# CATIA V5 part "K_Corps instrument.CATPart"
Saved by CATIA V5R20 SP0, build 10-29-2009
Part number: Corps instrument
Material "Noyer": density 609 kg/m3, Young's modulus 1.16e+10 Pa
Material "Noyer": density 609 kg/m3, Young's modulus 1.16e+10 Pa
Material "Sapin": density 500 kg/m3, Young's modulus 1.7e+10 Pa, Poisson ratio 0.45, thermal expansion 3.75e-06 1/K
Bounding box of the stored display mesh (mm): x -70 to 114.339, y -224.999 to 224.999, z -164 to 1030.632
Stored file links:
  G:\Khaled_CFAO_2011\ST2M\ST2M_GR2\amorin\Khaled\CAD_Modification\K_Corps instrument.CATPart
  C:\Program Files\Dassault Systemes\B20\win_b64\startup\materials\French\Catalog.CATMaterial
  C:\Program Files\Dassault Systemes\B20\win_b64\startup\materials\beech.jpg
  C:\Program Files\Dassault Systemes\B20\win_b64\startup\materials\wild_walnut.jpg
  C:\Program Files\Dassault Systemes\B20\win_b64\startup\materials\red_wood.jpg
  C:\Program Files\Dassault Systemes\B20\win_b64\startup\materials\mahogany.jpg
  C:\Program Files\Dassault Systemes\B20\win_b64\startup\materials\bright_oak.jpg
  C:\Program Files\Dassault Systemes\B20\win_b64\startup\materials\wild_cherry.jpg
  C:\Program Files\Dassault Systemes\B20\win_b64\startup\materials\pinetree.jpg
  C:\Program Files\Dassault Systemes\B20\win_b64\startup\materials\rosewood.jpg
  C:\Program Files\Dassault Systemes\B20\win_b64\startup\materials\walnut.jpg
  C:\Program Files\Dassault Systemes\B20\win_b64\startup\materials\alpin_fir.jpg
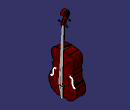
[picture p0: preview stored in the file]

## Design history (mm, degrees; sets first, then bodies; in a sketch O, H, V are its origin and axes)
Set1
  Plane1: type Angle, RefPlane yz-plane, Direction edge [face of Pad1 from Sketch1.L3 | end face of Pad1], Angle 5
Body1 (main body)
  Sketch1 on yz-plane, origin (0, 0, 0), H (0, 1, 0), V (0, 0, 1)
    arc A1 centre (-61, 0) radius 164 from (-217.1922, 50) to (-61, -164) ccw
    point P2 (-217.1922, 50)
    point P3 (-61, -164)
    line L1 (-61, -164) -> (-61, -154)
    point P4 (-61, -154)
    point P5 (0, 50)
    point P6 (61, -154)
    point P7 (61, -164)
    point P8 (217.1922, 50)
    point P9 (61, 0)
    arc A2 centre (61, 0) radius 164 from (217.1922, 50) to (61, -164) cw
    line L2 (61, -164) -> (61, -154)
    point P10 (0, 50)
    line L3 (-61, -154) -> (61, -154)
    arc A3 centre (-61, 0) radius 164 from (-217.1922, 50) to (-199.9767, 87.0717) cw
    point P12 (-204.3922, 79.5907)
    point P13 (-197.6963, 90.6097)
    line L4 (-200.0931, 94.1702) -> (-204.012, 99.9916)
    point P14 (-204.012, 99.9916)
    line L5 (-204.012, 99.9916) -> (-202.1596, 101.2916)
    point P15 (-202.1596, 101.2916)
    line L6 (-202.1596, 101.2916) -> (-196.9559, 99.2887)
    point P16 (-192.7457, 97.6682)
    arc A4 centre (-321.9325, 193.4393) radius 160.8146 from (-190.0619, 101.3986) to (-164.0477, 223.9964) ccw
    point P17 (-321.9325, 193.4393)
    arc A5 centre (-194.8558, 104.7446) radius 5.8462 from (-190.0619, 101.3986) to (-196.9559, 99.2887) cw
    point P18 (-190.0619, 101.3986)
    point P19 (-196.9559, 99.2887)
    arc A6 centre (-205.4985, 90.5313) radius 6.5161 from (-199.9767, 87.0717) to (-200.0931, 94.1702) ccw
    point P21 (-199.9767, 87.0717)
    point P22 (-200.0931, 94.1702)
    point P24 (-165.5658, 231)
    line L7 (-172.3837, 229.3623) -> (-176, 228.4936)
    point P25 (-176, 228.4936)
    line L8 (-176, 228.4936) -> (-177.6873, 231)
    point P26 (-177.6873, 231)
    line L9 (-177.6873, 231) -> (-171.3021, 235.481)
    point P27 (-167.4652, 238.1738)
    arc A7 centre (-170.7817, 222.6931) radius 6.8589 from (-164.0477, 223.9964) to (-172.3837, 229.3623) ccw
    point P28 (-164.0477, 223.9964)
    point P29 (-172.3837, 229.3623)
    axis line L10 (0, -177) -> (0, 597)
    point P31 (0, -177)
    point P33 (0, 489)
    arc A8 centre (-5.9488, -152.8379) radius 641.8655 from (0, 489) to (-108.317, 480.8119) ccw
    arc A9 centre (-94.4955, 395.258) radius 86.6631 from (-108.317, 480.8119) to (-181.1554, 396) ccw
    point P36 (-181.1554, 396)
    arc A10 centre (82.1641, 393.7455) radius 263.3292 from (-181.1554, 396) to (-157.7256, 285.14) ccw
    point P38 (-142.2045, 255.9015)
    point P39 (0, 489)
    point P40 (-108.317, 480.8119)
    arc A11 centre (-194.476, 268.502) radius 40.3412 from (-157.7256, 285.14) to (-171.3021, 235.481) cw
    point P41 (-157.7256, 285.14)
    point P42 (-171.3021, 235.481)
    point P44 (204.3922, 79.5907)
    point P45 (197.6963, 90.6097)
    point P46 (204.012, 99.9916)
    point P47 (202.1596, 101.2916)
    point P48 (192.7457, 97.6682)
    point P49 (190.0619, 101.3986)
    point P50 (196.9559, 99.2887)
    point P52 (199.9767, 87.0717)
    point P53 (200.0931, 94.1702)
    point P55 (165.5658, 231)
    point P56 (176, 228.4936)
    point P57 (177.6873, 231)
    point P58 (167.4652, 238.1738)
    point P59 (164.0477, 223.9964)
    point P60 (172.3837, 229.3623)
    point P62 (0, 489)
    point P64 (181.1554, 396)
    point P66 (142.2045, 255.9015)
    point P67 (0, 489)
    point P68 (108.317, 480.8119)
    point P69 (157.7256, 285.14)
    point P70 (171.3021, 235.481)
    line L11 (200.0931, 94.1702) -> (204.012, 99.9916)
    line L12 (204.012, 99.9916) -> (202.1596, 101.2916)
    line L13 (202.1596, 101.2916) -> (196.9559, 99.2887)
    arc A12 centre (321.9325, 193.4393) radius 160.8146 from (190.0619, 101.3986) to (164.0477, 223.9964) cw
    arc A13 centre (194.8558, 104.7446) radius 5.8462 from (190.0619, 101.3986) to (196.9559, 99.2887) ccw
    arc A14 centre (205.4985, 90.5313) radius 6.5161 from (199.9767, 87.0717) to (200.0931, 94.1702) cw
    line L14 (172.3837, 229.3623) -> (176, 228.4936)
    line L15 (176, 228.4936) -> (177.6873, 231)
    line L16 (177.6873, 231) -> (171.3021, 235.481)
    arc A15 centre (170.7817, 222.6931) radius 6.8589 from (164.0477, 223.9964) to (172.3837, 229.3623) cw
    arc A16 centre (5.9488, -152.8379) radius 641.8655 from (0, 489) to (108.317, 480.8119) cw
    arc A17 centre (94.4955, 395.258) radius 86.6631 from (108.317, 480.8119) to (181.1554, 396) cw
    arc A18 centre (-82.1641, 393.7455) radius 263.3292 from (181.1554, 396) to (157.7256, 285.14) cw
    arc A19 centre (194.476, 268.502) radius 40.3412 from (157.7256, 285.14) to (171.3021, 235.481) ccw
    point P74 (217.1922, 50)
    point P75 (204.3922, 79.5907)
    point P76 (199.9767, 87.0717)
    arc A20 centre (61, 0) radius 164 from (217.1922, 50) to (199.9767, 87.0717) ccw
    angle L4 L5 = 91.1128
    angle L6 L5 = 123.8872
    radius A5 = 5.8462
    radius A6 = 6.5161
    radius A7 = 6.8589
    radius A11 = 40.3412
    vertical: L1 V, L10 V
    coincidence: P5 V, P5 P10, A3 P12, P12 A1, P13 A1, P16 A3, L6 P9, A4 P16, L6 P16, A3 P13, L4 P13, P24 A4, L7 P17, P27 A4, L7 P24, P31 V, P33 L10, P38 L9, A10 P38, L9 P27
    symmetry: P4 P6 V, P3 P7 V, P2 P8 V, A1 A2 V, L1 L2 V, P5 P10 V, P12 P44 L10, P13 P45 L10, P14 P46 L10, P15 P47 L10, P16 P48 L10, P18 P49 L10, P19 P50 L10, P21 P52 L10, P22 P53 L10, P24 P55 L10, P25 P56 L10, P26 P57 L10, P27 P58 L10, P28 P59 L10, P29 P60 L10, P33 P62 L10, P36 P64 L10, P38 P66 L10, P39 P67 L10, P40 P68 L10, P41 P69 L10, P42 P70 L10, L4 L11 L10, L5 L12 L10, L6 L13 L10, A4 A12 L10, A5 A13 L10, A6 A14 L10, L7 L14 L10, L8 L15 L10, L9 L16 L10, A7 A15 L10, A8 A16 L10, A9 A17 L10, A10 A18 L10, A11 A19 L10, P2 P74 L10, P12 P75 L10, P21 P76 L10, A3 A20 L10
    horizontal: L3 H
    tangency: L4 A2, L5 A3, A4 A1, A5 L6, A5 A4, A6 A3, A6 L4, A7 L7, A7 A4, A9 L9, A10 A9, A9 A8, A11 A10, A11 L9
    parallelism: L8 L4, L9 L5
  Pad1: profile Sketch1, direction (1, 0, 0), length 70, mirrored extent
  Sketch2 on face of Pad1 from Sketch1.L3, origin (-8.5202, -2.8573, -154), H (1, 0, 0), V (0, -1, 0)
    point P1 (0, 0)
  Hole1: placed by Sketch2, at (-8.5202, -2.8573, -154) direction (0, 0, 1), diameter 34, depth 70, type TaperedType, Diameter 34, Sketch Sketch2, Profile a sketch, ThreadDepth 10, DiameterThread 37.4, Pas 1, Angle 5
  Fillet1: radius 3, on edge [start face of Pad1 | face of Pad1 from Sketch1.A1]; edge [start face of Pad1 | face of Pad1 from Sketch1.L3]; edge [start face of Pad1 | face of Pad1 from Sketch1.L2]; edge [start face of Pad1 | face of Pad1 from Sketch1.A2]
  Sketch3 on end face of Pad1, origin (70, 0, 0), H (0, 1, 0), V (0, 0, 1)
    spline S1 through (117.3427, 183.1693) (128, 185) (144, 173) (154.3427, 148.1693) (170.8675, 66.9958) (181, 61)
    spline S2 through (179, 51) (163, 62) (152, 91) (150, 113) (150, 137) (137.8996, 169.4934) (130.8996, 176.4934)
    arc A1 centre (122.784, 177.1161) radius 8.1394 from (117.3427, 183.1693) to (130.8996, 176.4934) ccw
    point P1 (130.8996, 176.4934)
    point P3 (117.3427, 183.1693)
    arc A2 centre (185.6857, 54.8629) radius 7.7214 from (179, 51) to (181, 61) ccw
    point P4 (181, 61)
    point P6 (179, 51)
    point P7 (-130.8996, 176.4934)
    point P9 (-117.3427, 183.1693)
    point P10 (-181, 61)
    point P12 (-179, 51)
    spline S3 through (-117.3427, 183.1693) (-128, 185) (-144, 173) (-154.3427, 148.1693) (-170.8675, 66.9958) (-181, 61)
    spline S4 through (-179, 51) (-163, 62) (-152, 91) (-150, 113) (-150, 137) (-137.8996, 169.4934) (-130.8996, 176.4934)
    arc A3 centre (-122.784, 177.1161) radius 8.1394 from (-117.3427, 183.1693) to (-130.8996, 176.4934) cw
    arc A4 centre (-185.6857, 54.8629) radius 7.7214 from (-179, 51) to (-181, 61) cw
    point P13 (130.8996, 176.4934)
    point P14 (117.3427, 183.1693)
    point P15 (181, 61)
    point P16 (179, 51)
    point P17 (-181, 61)
    point P18 (-117.3427, 183.1693)
    point P19 (170.8675, 66.9958)
    point P20 (-170.8675, 66.9958)
    point P21 (154.3427, 148.1693)
    point P22 (-154.3427, 148.1693)
    point P23 (144, 173)
    point P24 (-144, 173)
    point P25 (128, 185)
    point P26 (-128, 185)
    point P27 (-130.8996, 176.4934)
    point P28 (-179, 51)
    point P29 (137.8996, 169.4934)
    point P30 (-137.8996, 169.4934)
    point P31 (150, 137)
    point P32 (-150, 137)
    point P33 (150, 113)
    point P34 (-150, 113)
    point P35 (152, 91)
    point P36 (-152, 91)
    point P37 (163, 62)
    point P38 (-163, 62)
    coincidence: P13 P1, P14 P3, P15 P4, P16 P6, P7 P27, P9 P18, P10 P17, P12 P28
    symmetry: P1 P7 V, P3 P9 V, P4 P10 V, P6 P12 V, S1 S3 V, S2 S4 V, A1 A3 V, A2 A4 V, P15 P17 V, P14 P18 V, P19 P20 V, P21 P22 V, P23 P24 V, P25 P26 V, P13 P27 V, P16 P28 V, P29 P30 V, P31 P32 V, P33 P34 V, P35 P36 V, P37 P38 V
  Pocket1: profile Sketch3, direction (-1, 0, 0), length 70
  Sketch4 on Plane1, origin (82.1587, 0, -15.0258), H (0, 1, 0), V (0.0872, 0, 0.9962)
    point P1 (0, 3.4943)
    line L1 (0, 3.4943) -> (29.9538, 3.4943)
    point P2 (29.9538, 3.4943)
    line L2 (29.9538, 3.4943) -> (29.9538, -12.5057)
    point P3 (29.9538, -12.5057)
    arc A1 centre (67.3869, -48.2944) radius 51.7888 from (29.9538, -12.5057) to (15.6291, -46.5057) ccw
    point P5 (15.6291, -46.5057)
    line L3 (15.6291, -46.5057) -> (8, -130)
    point P6 (8, -130)
    arc A2 centre (-4.2407, -128.8815) radius 12.2916 from (8, -130) to (4.2054, -137.8118) cw
    point P8 (0, -140.4185)
    point P9 (0, -140.4185)
    point P10 (-29.9538, 3.4943)
    point P11 (0, 3.4943)
    line L4 (0, 3.4943) -> (-29.9538, 3.4943)
    point P12 (-29.9538, -12.5057)
    line L5 (-29.9538, 3.4943) -> (-29.9538, -12.5057)
    point P13 (-15.6291, -46.5057)
    arc A3 centre (-67.3869, -48.2944) radius 51.7888 from (-29.9538, -12.5057) to (-15.6291, -46.5057) cw
    point P15 (-8, -130)
    line L6 (-15.6291, -46.5057) -> (-8, -130)
    point P16 (0, -140.4185)
    arc A4 centre (4.2407, -128.8815) radius 12.2916 from (-8, -130) to (-4.2054, -137.8118) ccw
    arc A5 centre (0, -133.3653) radius 6.1202 from (-4.2054, -137.8118) to (4.2054, -137.8118) ccw
    radius A5 = 6.1202
    coincidence: P1 V, A2 P8, P8 V, P16 P9, A4 P16, A2 P9, P1 P11
    horizontal: L1 H
    vertical: L2 V
    tangency: A1 L1, A2 L3, A5 A4, A5 A2
    symmetry: P2 P10 V, P1 P11 V, L1 L4 V, P3 P12 V, L2 L5 V, P5 P13 V, A1 A3 V, P6 P15 V, L3 L6 V, P9 P16 V, A2 A4 V
  Pad2: profile Sketch4, direction (0.9962, 0, -0.0872), length 16
  Sketch5 on xy-plane, origin (0, 0, 0), H (1, 0, 0), V (0, 1, 0)
    point P1 (70, 13)
    line L1 (70, 13) -> (70, 31)
    point P2 (70, 31)
    line L2 (70, 31) -> (75, 31)
    point P3 (75, 31)
    line L3 (75, 31) -> (75, 25)
    point P4 (75, 25)
    line L4 (75, 25) -> (96, 25)
    point P5 (96, 25)
    arc A1 centre (34.7759, -2.9138) radius 67.2873 from (96, 25) to (102, 0) cw
    point P7 (102, 0)
    point P8 (70, -13)
    point P9 (70, -31)
    point P10 (75, -31)
    point P11 (75, -25)
    point P12 (96, -25)
    point P13 (102, 0)
    line L5 (70, -13) -> (70, -31)
    line L6 (70, -31) -> (75, -31)
    line L7 (75, -31) -> (75, -25)
    line L8 (75, -25) -> (96, -25)
    arc A2 centre (34.7759, 2.9138) radius 67.2873 from (96, -25) to (102, 0) ccw
    line L9 (70, -13) -> (70, 13)
    reference projected line E1 (70, 108.317) -> (70, 0) from edge [face of Pad1 from Sketch1.A16 | end face of Pad1]
    vertical: L1 V, L3 V, L9 V
    horizontal: L2 H, L4 H
    coincidence: P7 H, L9 E1, P7 P13
    symmetry: P1 P8 H, P2 P9 H, P3 P10 H, P4 P11 H, P5 P12 H, P7 P13 H, L1 L5 H, L2 L6 H, L3 L7 H, L4 L8 H, A1 A2 H
Body2 "Corps Cello", material "Noyer"
  Extract1: ExtractElem end face of Pad1
  CloseSurface1: CloseElement Extract1
  Boundary1: Boundary face of CloseSurface1
  Extract2: ExtractElem edge of Boundary1
  Boundary2: Boundary face of CloseSurface1
  Extract3: ExtractElem edge of Boundary2
  Point1: type OnCurve, Support edge [face of CloseSurface1 | face of CloseSurface1], Length 108.7561
  Plane2: type OffsetPt, RefPlane yz-plane, RefPoint Point1
  Plane3: type Angle, RefPlane Plane2, Direction edge [face of CloseSurface1 | face of CloseSurface1], Angle 177
Body3 "Support Cords"
  Extract4: ExtractElem end face of Pad2
  CloseSurface2: CloseElement Extract4
  Fillet2: radius 5, on face of CloseSurface2
Body4 "Support"
  Sketch6, origin (0, 0, 0), H (1, 0, 0), V (0, 1, 0), geometry linked from another document
  Pad3: profile Sketch6, direction (0, 0, 1), length 5
Body5 "Bras"
  Plane4: type OffsetPt, RefPlane Plane3, RefPoint Point1
  Sketch7 on Plane4, origin (95.1756, 0, 8.6209), H (0, -1, 0), V (-0.0523, 0, 0.9986)
    axis line L1 (0, 820.5391) -> (0, -58)
    point P1 (0, 820.5391)
    line L2 (-8.9107, 816.5076) -> (-25.5352, 80.7809)
    line L3 (-15.5223, 70.5391) -> (0, 70.5391)
    point P3 (0, 70.5391)
    line L4 (-4.7872, 820.5391) -> (0, 820.5391)
    arc A1 centre (-4.7872, 816.4145) radius 4.1246 from (-4.7872, 820.5391) to (-8.9107, 816.5076) ccw
    point P4 (-4.7872, 820.5391)
    point P5 (-8.9107, 816.5076)
    arc A2 centre (-15.5223, 80.5546) radius 10.0155 from (-15.5223, 70.5391) to (-25.5352, 80.7809) cw
    point P7 (-15.5223, 70.5391)
    point P8 (-25.5352, 80.7809)
    point P10 (0, 70.5391)
    point P11 (15.5223, 70.5391)
    line L5 (15.5223, 70.5391) -> (0, 70.5391)
    point P12 (25.5352, 80.7809)
    arc A3 centre (15.5223, 80.5546) radius 10.0155 from (15.5223, 70.5391) to (25.5352, 80.7809) ccw
    point P14 (8.9107, 816.5076)
    line L6 (8.9107, 816.5076) -> (25.5352, 80.7809)
    point P15 (4.7872, 820.5391)
    arc A4 centre (4.7872, 816.4145) radius 4.1246 from (4.7872, 820.5391) to (8.9107, 816.5076) cw
    point P17 (0, 820.5391)
    line L7 (4.7872, 820.5391) -> (0, 820.5391)
    radius A1 = 4.1246
    radius A2 = 10.0155
    distance P3 P1 = 750
    coincidence: P1 V, P3 L1, P1 P17, P3 P10
    vertical: L1 V
    horizontal: L3 H, L4 H
    tangency: A1 L4, A1 L2, A2 L3, A2 L2
    symmetry: P3 P10 L1, P7 P11 L1, L3 L5 L1, P8 P12 L1, A2 A3 L1, P5 P14 L1, L2 L6 L1, P4 P15 L1, A1 A4 L1, P1 P17 L1, L4 L7 L1
  Pad4: profile Sketch7, direction (0.9986, 0, 0.0523), length 14
  Sketch8 on zx-plane, origin (0, 0, 0), H (-1, 0, 0), V (0, 0, 1)
    spline S1 through (-50.7839, 974.3686) (-62.7592, 966.489) (-79.0622, 967.4069) (-93.0952, 995.071) (-64.8368, 1025.6753) (-30.6912, 1029.9911) (9.3414, 1002.9183) (13.2662, 944.4564) (-10.6749, 911.4981) (-42.8581, 827.5205)
    line L1 (-42.8581, 827.5205) -> (-47.2334, 827.5205)
    point P1 (-42.8581, 827.5205)
    spline S2 through (-50.7839, 974.3686) (-32.6493, 987.5643) (-8.9842, 973.2503) (-9.46, 955.3261) (-30.8178, 927.8696) (-62.9524, 890.7374) (-78.4478, 827.5205)
    line L2 (-47.2334, 827.5205) -> (-78.4478, 827.5205)
    point P3 (-78.4478, 827.5205)
    point P4 (-42.8581, 827.5205)
    point P5 (-50.7839, 974.3686)
    point P6 (-50.7839, 974.3686)
    point P7 (-78.4478, 827.5205)
    horizontal: L1 H, L2 H
    coincidence: P1 P4, P5 P6, P7 L1, P7 P3
Body6 "Extremite", material "Noyer"
  Sketch9, origin (0, 0, 0), H (-1, 0, 0), V (0, 0, 1), geometry linked from another document
  Pad5: profile Sketch9, direction (0, 1, 0), length 20, mirrored extent
  Sketch10 on end face of Pad5, origin (0, 20, 0), H (-1, 0, 0), V (0, 0, 1)
  Plane5: type Offset, RefPlane start face of Pad5, Offset 20
  Sketch11 on Plane5, origin (0, 0, 0), H (-1, 0, 0), V (0, 0, 1)
    circle A1 centre (-28.7579, 966.6352) radius 24.3335
  Pad6: profile Sketch11, direction (0, 1, 0), length 30, mirrored extent
  FaceFillet1: Radius 10, Face1 end face of Pad5, Face2 face of Pad6 from Sketch11.A1, ConicRatio 0.5
  FaceFillet2: Radius 10, Face1 start face of Pad5, Face2 face of Pad6 from Sketch11.A1, ConicRatio 0.5
  Sketch12 on Plane5, origin (0, 0, 0), H (-1, 0, 0), V (0, 0, 1)
    circle A1 centre (-28.911, 967.6271) radius 11.463
  Pad7: profile Sketch12, direction (0, 1, 0), length 40, mirrored extent
  Fillet3: radius 5, on end face of Pad7
  Fillet4: radius 5, on start face of Pad7
  Sketch13 on zx-plane, origin (0, 0, 0), H (-1, 0, 0), V (0, 0, 1)
    line L1 (-52.2712, 827.285) -> (-70, 489)
    line L2 (-70, 489) -> (68.4968, 489)
    line L3 (68.4968, 489) -> (68.4968, 504.1304)
    line L4 (68.4968, 504.1304) -> (-52.5933, 523.1868)
    line L5 (-52.5933, 523.1868) -> (-44.6071, 826.8833)
    line L6 (-44.6071, 826.8833) -> (-52.2712, 827.285)
    reference projected line E1 (-52.4429, 824.0096) -> (-90.9479, 89.2911) from edge [face of Pad4 from Sketch7.L2 | start face of Pad4]
    reference projected line E2 (70, 489) -> (-70, 489) from edge [face of CloseSurface1 | face of CloseSurface1]
    horizontal: L2 H
    vertical: L3 V
    perpendicularity: L6 L1
    coincidence: L1 E1, L2 E2
Body7, material "Sapin"
  Pad8: profile Sketch13, direction (0, 1, 0), length 8, mirrored extent
  Fillet5: radius 5, on face of Pad8 from Sketch13.L5; face of Pad8 from Sketch13.L4; face of Pad8 from Sketch13.L3
Body8 "Cles reglages"
  Point2: type OnSurface, Support face of Pad5, Length 0, Direction edge [face of Pad5 | face of Pad5]
  Plane6: type OffsetPt, RefPlane yz-plane, RefPoint Point2
  Sketch14 on Plane6, origin (62.8406, 0, 0), H (0, 1, 0), V (0, 0, 1)
    reference projected line E1 (20, 987.5766) -> (20, 827.5205) from edge [face of Pad5 | end face of Pad5]
    line L1 (20, 848.7396) -> (20, 838.7396)
    line L2 (20, 838.7396) -> (45, 838.7396)
    line L3 (20, 848.7396) -> (45, 848.7396)
    point P1 (52.2296, 848.7396)
    arc A1 centre (63.1384, 843.7396) radius 12 from (55.0769, 852.6285) to (55.0769, 834.8507) cw
    arc A2 centre (45, 863.7396) radius 15 from (55.0769, 852.6285) to (45, 848.7396) cw
    point P2 (52.2296, 838.7396)
    arc A3 centre (45, 823.7396) radius 15 from (55.0769, 834.8507) to (45, 838.7396) ccw
    line L4 (-20, 868.345) -> (-20, 858.345)
    line L5 (-20, 868.345) -> (-45, 868.345)
    line L6 (-20, 858.345) -> (-45, 858.345)
    arc A4 centre (-63.1384, 863.345) radius 12 from (-55.0769, 854.4561) to (-55.0769, 872.2339) cw
    arc A5 centre (-45, 883.345) radius 15 from (-55.0769, 872.2339) to (-45, 868.345) ccw
    arc A6 centre (-45, 843.345) radius 15 from (-55.0769, 854.4561) to (-45, 858.345) cw
    reference projected line E2 (-20, 987.5766) -> (-20, 827.5205) from edge [start face of Pad5 | face of Pad5]
    radius A3 = 15
    radius A5 = 15
    radius A6 = 15
    length L6 = 25
    length L2 = 25
    distance L2 L3 = 10
    distance L6 L5 = 10
    radius A2 = 15
    radius A1 = 12
    radius A4 = 12
    vertical: L1 V, L4 V
    horizontal: L2 H, L3 H, L5 H, L6 H
    coincidence: E1 L1, A1 P1, L3 P1, A1 P2, L2 P2, L4 E2
    tangency: A2 A1, A2 L3, A3 L2, A3 A1, A5 A4, A5 L5, A6 A4, A6 L6
  Pad9: profile Sketch14, direction (1, 0, 0), length 8
  Fillet6: radius 5, on end face of Pad9
  Fillet7: radius 2, on start face of Pad9
  Fillet8: radius 2, on start face of Pad9
  Fillet9: radius 5, on end face of Pad9
Body9 "Cles"
  Extract5: ExtractElem Body8
  Translate1: Direction edge [end face of Pad4 | face of Pad4 from Sketch7.L2], Length -65, ToTransfor Extract5
  Translate2: Direction edge [end face of Pad5 | face of Pad5], Length -40, ToTransfor Translate1
  CloseSurface3: CloseElement Translate2
Body10 "Cords"
  Plane7: type Offset, RefPlane end face of Pad4, Offset 5, reversed
  Sketch15 on Plane7, origin (114.3394, 0, 5.9923), H (0, -1, 0), V (-0.0523, 0, 0.9986)
    line L1 (-7.4989, 822.4248) -> (-23.6682, 0)
    point P1 (-23.6682, 0)
    point P2 (-7.4989, 822.4248)
    line L2 (0, 822.5538) -> (-10.9426, 0)
    point P3 (0, 822.5538)
    point P4 (-10.9426, 0)
    point P5 (7.4921, 822.2093)
    point P6 (14.9921, 822.2093)
    point P7 (23.6682, 0)
    point P8 (7.4989, 822.4248)
    line L3 (7.4989, 822.4248) -> (23.6682, 0)
    point P9 (10.9426, 0)
    point P10 (0, 822.5538)
    line L4 (0, 822.5538) -> (10.9426, 0)
    point P11 (0, -159.7499)
    distance P2 P3 = 7.5
    distance P3 P5 = 7.5
    distance P5 P6 = 7.5
    coincidence: P1 H, P3 V, P4 H, P11 V
    symmetry: P1 P7 V, P2 P8 V, L1 L3 V, P4 P9 V, P3 P10 V, L2 L4 V
  Plane8: type Offset, RefPlane face of CloseSurface2, Offset 5, reversed
  Sketch16 on Plane8, origin (103.7593, 0, -9.0778), H (0, -1, 0), V (0.0872, 0, 0.9962)
    line L1 (-23.6682, 15.9348) -> (-3.4658, -146.4123)
    point P1 (-23.6682, 15.9348)
    point P2 (-3.4658, -146.4123)
    reference projected point E1 (-23.6682, 15.9348) from Sketch15.P1
    line L2 (-10.9426, 15.9348) -> (0, -147.13)
    point P3 (0, -147.13)
    point P4 (-10.9426, 15.9348)
    reference projected point E2 (-10.9426, 15.9348) from Sketch15.P4
    point P5 (3.4658, -146.4123)
    point P6 (23.6682, 15.9348)
    line L3 (23.6682, 15.9348) -> (3.4658, -146.4123)
    point P7 (0, -147.13)
    point P8 (10.9426, 15.9348)
    line L4 (10.9426, 15.9348) -> (0, -147.13)
    coincidence: P1 E1, P3 V, E2 P4
    symmetry: P2 P5 V, P1 P6 V, L1 L3 V, P3 P7 V, P4 P8 V, L2 L4 V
